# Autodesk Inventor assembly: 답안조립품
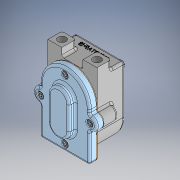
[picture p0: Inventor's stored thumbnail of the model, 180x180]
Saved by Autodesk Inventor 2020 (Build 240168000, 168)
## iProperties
Created: 2024-03
Part Number: 답안조립품
Document SubType Name: Assembly
Designer: 1강의실14
Author: 1강의실14
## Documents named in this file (9)
- C:\Users\1강의실14\Desktop\740304V1012\답안조립품.iam
- C:\Users\1강의실14\Desktop\740304V1012\본체.ipt
- C:\Users\1강의실14\Desktop\740304V1012\오일레스 부시.ipt
- C:\Users\1강의실14\Desktop\740304V1012\구동기어.ipt
- C:\Users\1강의실14\Desktop\740304V1012\오일 실 14 25 7.ipt
- C:\Users\1강의실14\Desktop\740304V1012\스퍼기어.ipt
- C:\Users\1강의실14\Desktop\740304V1012\가스켓.ipt
- C:\Users\1강의실14\Desktop\740304V1012\커버.ipt
- C:\Users\1강의실14\Desktop\740304V1012\육각 소켓 머리 볼트 M5x12.ipt
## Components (2 placed, 2 different names)
1. 구동기어:1
2. 가스켓:1
